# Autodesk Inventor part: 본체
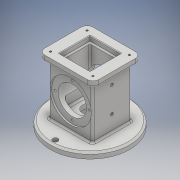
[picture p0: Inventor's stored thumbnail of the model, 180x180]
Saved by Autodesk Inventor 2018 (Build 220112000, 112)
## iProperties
Created: 2019-08
Part Number: 본체
Material: Generic
Document SubType Name: Modeling
Designer: Administrator
Density: 1 g/cm^3
Appearance: Default
Author: Administrator
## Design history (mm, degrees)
sketch "스케치1"
  geometry: C1 r 67.5 at (0, 0); 1 further point
  constraints: 1 centre point, 1 coincident
  dimensions: "d0" = 135 diameter of C1
extrude "돌출1" new body sketch "스케치1" distance "d1" = 10; taper "d2" = 0 deg
sketch "스케치4"
  geometry: L1 (37, -33)-(-37, -33); L2 (-37, -33)-(-37, 33); L3 (-37, 33)-(37, 33); L4 (37, 33)-(37, -33); L5 (37, -33)-(-37, 33); L6 (-37, -33)-(37, 33); 1 further point
  constraints: 12 end point, 2 midpoint, 2 parallel, 1 horizontal, 1 perpendicular
  dimensions: "d11" = 74 distance of L2.end L3.end; "d12" = 66 distance of L1.end L2.end
extrude "돌출3" join sketch "스케치4" distance "d13" = 88; taper "d14" = 0 deg
sketch "스케치5"
  geometry: L1 (46, -41)-(-46, -41); L2 (-46, -41)-(-46, 41); L3 (-46, 41)-(46, 41); L4 (46, 41)-(46, -41); L5 (46, -41)-(-46, 41); L6 (-46, -41)-(46, 41); 1 further point
  constraints: 12 end point, 2 midpoint, 2 parallel, 1 horizontal, 1 perpendicular
  dimensions: "d15" = 92 distance of L2.end L3.end; "d16" = 82 distance of L1.end L2.end
extrude "돌출4" join sketch "스케치5" distance "d17" = 10; taper "d18" = 0 deg
sketch "스케치6"
  geometry: L1 (46, -41)-(-46, -41) reference; L2 (-46, -41)-(-46, 41) reference; L3 (-46, 41)-(46, 41) reference; L4 (46, 41)-(46, -41) reference; L5 (-37, 33)-(-37, -33) reference; L6 (-37, -33)-(37, -33) reference; L7 (37, -33)-(37, 33) reference; L8 (37, 33)-(-37, 33) reference; L9 (26, -26)-(-26, -26); L10 (-26, -26)-(-26, 26); L11 (-26, 26)-(26, 26); L12 (26, 26)-(26, -26); L13 (26, -26)-(-26, 26); L14 (-26, -26)-(26, 26); C1 r 67.5 at (0, 0) reference; 1 further point
  constraints: 12 end point, 2 midpoint, 2 parallel, 1 horizontal, 1 perpendicular
  dimensions: "d19" = 52 distance of L10.end L11.end; "d20" = 52 distance of L9.end L10.end
extrude "돌출5" cut sketch "스케치6" distance "d21" = 8; taper "d22" = 0 deg
sketch "스케치8"
  geometry: L1 (22, 22)-(-22, 22); L2 (-22, 22)-(-22, -22); L3 (-22, -22)-(22, -22); L4 (22, -22)-(22, 22); L5 (22, 22)-(-22, -22); L6 (-22, 22)-(22, -22); 1 further point
  constraints: 12 end point, 2 midpoint, 2 parallel, 1 horizontal, 1 perpendicular
  dimensions: "d25" = 44 distance of L1.end L2.end; "d26" = 44 distance of L2.end L3.end
extrude "돌출6" cut sketch "스케치8" distance "d27" = 74; taper "d28" = 0 deg
sketch "스케치9"
  geometry: C1 r 25 at (0, 0); 1 further point
  constraints: 1 centre point, 1 coincident
  dimensions: "d29" = 50 diameter of C1
extrude "돌출7" cut sketch "스케치9" distance "d30" = 18; taper "d31" = 0 deg
sketch "스케치10"
  geometry: C1 r 12.5 at (0, 0); 1 further point
  constraints: 1 centre point, 1 coincident
  dimensions: "d32" = 25 diameter of C1
extrude "돌출8" cut sketch "스케치10" distance "d33" = 75.75; taper "d34" = 0 deg
sketch "스케치11"
  geometry: L1 (74, 0)-(0, 0) reference; L2 (74, 0)-(74, 88) reference; L3 (0, 88)-(74, 88) reference; L4 (0, 0)-(0, 88) reference; C1 r 35 at (37, 44); 1 further point
  constraints: 1 centre point
  dimensions: "d35" = 70 diameter of C1
extrude "돌출9" cut sketch "스케치11" distance "d36" = 3; taper "d37" = 0 deg
sketch "스케치12"
  geometry: C1 r 35 at (37, -44); 1 further point
  constraints: 1 centre point
  dimensions: "d39" = 70 diameter of C1
extrude "돌출10" cut sketch "스케치12" distance "d40" = 3; taper "d41" = 0 deg
sketch "스케치13"
  geometry: C1 r 35 at (0, 0) reference; C2 r 24 at (0, 0); 1 further point
  constraints: 1 centre point, 1 coincident
  dimensions: "d42" = 48 diameter of C2
extrude "돌출11" cut sketch "스케치13" distance "d43" = 163.75; taper "d44" = 0 deg
sketch "스케치14"
  geometry: C1 r 4.5 at (0, -59); C2 r 4.5 at (59, 0); C3 r 4.5 at (0, 59); 2 further points
  constraints: 3 centre point
  dimensions: "d46" = 9 diameter of C1; "d47" = 9 diameter of C2; "d48" = 9 diameter of C3
extrude "돌출12" cut sketch "스케치14" distance "d49" = 50; taper "d50" = 0 deg
sketch "스케치15"
  geometry: 2 further points
hole "구멍1" sketch "스케치15" at (37, 73) diameter "d52" = 3.242; stored, may be unused: countersink angle "d56" = 90 deg, drill point angle "d58" = 118 deg; dims "d53" = 4, "d54" = 4, "d55" = 2, "d57" = 6
sketch "스케치16"
  geometry: 5 further points
hole "구멍2" sketch "스케치16" at (-36, 31), (36, 31), (36, -31), (-36, -31) diameter "d64" = 3.242; stored, may be unused: countersink angle "d68" = 90 deg, drill point angle "d70" = 118 deg; dims "d65" = 4, "d66" = 4, "d67" = 2, "d69" = 6
sketch "스케치17"
  geometry: 3 further points
hole "구멍3" sketch "스케치17" at (-27, 33), (-70, 33) diameter "d73" = 4.917; stored, may be unused: countersink angle "d77" = 90 deg, drill point angle "d79" = 118 deg; dims "d74" = 12, "d75" = 4, "d76" = 2, "d78" = 17.1
fillet "모깎기1" dims "d80" = 10
chamfer "모따기1" distance "d81" = 3; stored, may be unused: second distance "d82" = 2, angle "d83" = 45 deg
fillet "모깎기2" dims "d84" = 3
chamfer "모따기2" distance "d85" = 1; stored, may be unused: second distance "d86" = 2, angle "d87" = 45 deg
node "솔리드1"
pattern_circular "원형 패턴1" dims angle "d60" = 360 deg
mirror "미러1"
node "투영된 루프3"
node "투영된 루프4"
node "투영된 루프8"
node "투영된 루프9"
